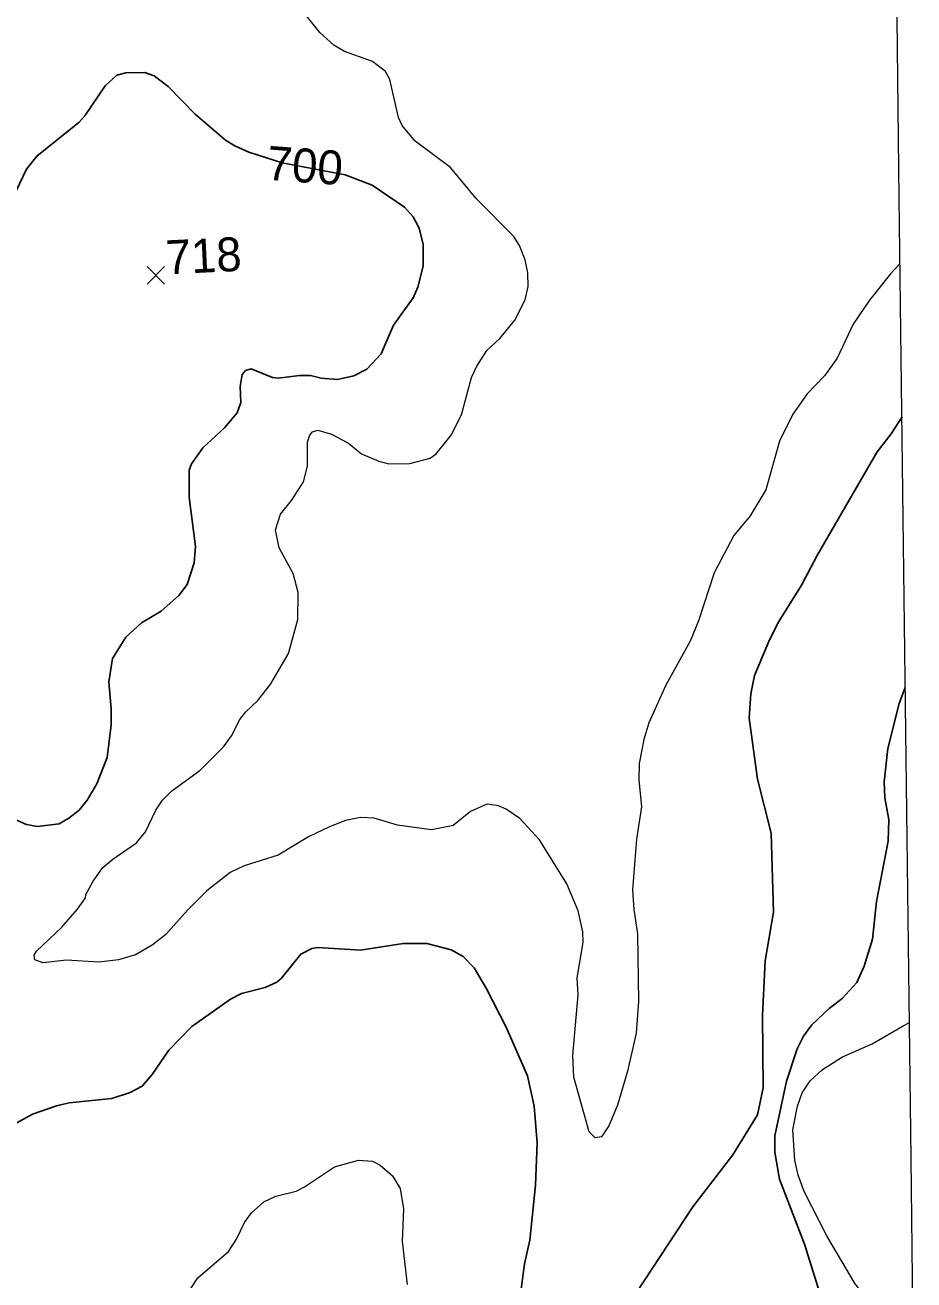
# Model space of a CAD drawing. Extents: x 265 to 291.4, y 7731.5 to 7759.6.
# Drawn here: x 289.153 to 291.245, y 7746.284 to 7749.237 of the extents above; entities that cross this region are included whole.
import ezdxf
from ezdxf.enums import TextEntityAlignment as Align

# ---------------------------------------------------------------- set-up
doc = ezdxf.new("R2010")
doc.units = 0
doc.header["$LTSCALE"] = 0.032
for name, color, linetype, lineweight in [('1', 7, 'Continuous', 25), ('2', 7, 'Continuous', 13), ('21', 7, 'Continuous', 25), ('61', 7, 'Continuous', 13), ('63', 7, 'Continuous', 25)]:
    doc.layers.add(name, color=color, linetype=linetype, lineweight=lineweight)

msp = doc.modelspace()

# ---------------------------------------------------------------- linework, layer by layer
at = {"layer": '1'}
for points in [[(289.1229, 7748.8292), (289.1563, 7748.8984), (289.1802, 7748.9286), (289.2797, 7749.0089), (289.2932, 7749.024), (289.3409, 7749.094), (289.3688, 7749.1195), (289.3902, 7749.1251), (289.4348, 7749.1259), (289.4563, 7749.1179), (289.4897, 7749.0924), (289.5533, 7749.0272), (289.6249, 7748.9667), (289.6464, 7748.9532), (289.6798, 7748.9381), (289.7577, 7748.9134), (289.9065, 7748.8848), (289.9694, 7748.8602), (290.0457, 7748.8084), (290.0664, 7748.7862), (290.0807, 7748.7592), (290.0902, 7748.721), (290.0895, 7748.6701), (290.0775, 7748.6207), (290.0664, 7748.5953), (290.0202, 7748.5308), (289.9908, 7748.4632), (289.9574, 7748.4274), (289.9264, 7748.4115), (289.8882, 7748.4028), (289.85, 7748.4059), (289.8246, 7748.4123), (289.7991, 7748.4123), (289.7482, 7748.4059), (289.7355, 7748.4075), (289.6846, 7748.4282), (289.6719, 7748.4242), (289.6639, 7748.4147), (289.6591, 7748.3869), (289.6607, 7748.3487), (289.6519, 7748.3248), (289.6225, 7748.289), (289.5708, 7748.2421), (289.5445, 7748.2047), (289.539, 7748.1896), (289.539, 7748.126), (289.5541, 7748.0098), (289.5509, 7747.9716), (289.5342, 7747.9207), (289.5143, 7747.8945), (289.473, 7747.8578), (289.4268, 7747.83), (289.3902, 7747.7966), (289.3584, 7747.7465), (289.3497, 7747.6916), (289.3552, 7747.628), (289.3552, 7747.5898), (289.3457, 7747.5134), (289.3218, 7747.4514), (289.2987, 7747.4132), (289.2797, 7747.3893), (289.2558, 7747.3702), (289.2327, 7747.3575), (289.1818, 7747.3511), (289.1564, 7747.3559), (289.0768, 7747.3901)], [(290.5906, 7746.2518), (290.725, 7746.4554), (290.8189, 7746.5779), (290.877, 7746.6718), (290.8905, 7746.7354), (290.8889, 7746.9057), (290.8945, 7747.0345), (290.9144, 7747.1491), (290.9088, 7747.3352), (290.877, 7747.4625), (290.8571, 7747.6057), (290.8611, 7747.663), (290.8698, 7747.7059), (290.9048, 7747.7903), (290.9271, 7747.8332), (290.9804, 7747.9191), (291.0178, 7747.9907), (291.1586, 7748.2325), (291.1912, 7748.2755), (291.217, 7748.3152)], [(291.2247, 7747.678), (291.2105, 7747.6407), (291.1833, 7747.5341), (291.1753, 7747.4562), (291.1769, 7747.418), (291.1856, 7747.3671), (291.1848, 7747.3161), (291.157, 7747.1746), (291.1475, 7747.0855), (291.1276, 7747.0218), (291.1109, 7746.9836), (291.0759, 7746.9462), (291.0456, 7746.9224), (291.0051, 7746.8842), (290.9852, 7746.8572), (290.9701, 7746.8277), (290.9454, 7746.7514), (290.9176, 7746.6225), (290.9176, 7746.5843), (290.9287, 7746.5207), (290.9876, 7746.3679), (291.0599, 7746.1372)], [(289.119, 7746.6455), (289.1699, 7746.6734), (289.2264, 7746.6933), (289.2566, 7746.7004), (289.3568, 7746.7108), (289.3998, 7746.7251), (289.4284, 7746.7394), (289.4523, 7746.7673), (289.4912, 7746.8245), (289.5453, 7746.8802), (289.636, 7746.9446), (289.6623, 7746.9574), (289.718, 7746.9717), (289.745, 7746.9844), (289.7562, 7746.994), (289.8015, 7747.0504), (289.8278, 7747.064), (289.8421, 7747.0663), (289.9423, 7747.06), (290.0425, 7747.0751), (290.0982, 7747.0751), (290.1555, 7747.0608), (290.1841, 7747.0449), (290.2096, 7747.0178), (290.2382, 7746.9701), (290.2851, 7746.8786), (290.3353, 7746.7641), (290.3512, 7746.6925), (290.3583, 7746.6066), (290.3543, 7746.5063), (290.3408, 7746.3775), (290.3281, 7746.3218)], [(290.3281, 7746.3218), (290.3146, 7746.2144), (290.2788, 7746.1213), (290.2462, 7746.0084), (290.243, 7745.9877), (290.2541, 7745.9773), (290.2756, 7745.9765)]]:
    msp.add_lwpolyline(points, dxfattribs=at)
at = {"layer": '2'}
for points in [[(289.823, 7748.2723), (289.8293, 7748.2795), (289.8421, 7748.2834), (289.8739, 7748.2747), (289.9137, 7748.2532), (289.9447, 7748.2278), (289.9853, 7748.2111), (290.0091, 7748.2047), (290.0585, 7748.2055), (290.1062, 7748.2182), (290.1205, 7748.2278), (290.1555, 7748.2723), (290.1802, 7748.3201), (290.204, 7748.4076), (290.2159, 7748.4346), (290.2398, 7748.4712), (290.27, 7748.4998), (290.3058, 7748.5428), (290.3297, 7748.5905), (290.3369, 7748.6223), (290.3361, 7748.6542), (290.3297, 7748.6844), (290.3168, 7748.7185), (290.3034, 7748.7393), (290.2144, 7748.8292), (290.1539, 7748.9023), (290.0712, 7748.9644), (290.0401, 7749.001), (290.0314, 7749.0201), (290.0115, 7749.1092), (290.0012, 7749.1283), (289.9702, 7749.1513), (289.9049, 7749.1752), (289.8795, 7749.1903), (289.8468, 7749.2197), (289.7991, 7749.2794)], [(291.2126, 7748.676), (291.19, 7748.6521), (291.1403, 7748.5897), (291.1021, 7748.5332), (291.0647, 7748.4529), (291.0345, 7748.4115), (290.9939, 7748.3694), (290.9597, 7748.3216), (290.9287, 7748.258), (290.8961, 7748.1435), (290.8595, 7748.0822), (290.8213, 7748.0361), (290.7752, 7747.9478), (290.7378, 7747.8348), (290.7187, 7747.7871), (290.6614, 7747.6837), (290.6209, 7747.5946), (290.6089, 7747.5556), (290.5986, 7747.4991), (290.5978, 7747.4609), (290.6041, 7747.3973), (290.5922, 7747.3209), (290.5827, 7747.2016), (290.5858, 7747.1555), (290.5946, 7747.0982), (290.597, 7746.9391), (290.5914, 7746.8643), (290.5707, 7746.7752), (290.5469, 7746.6949), (290.527, 7746.6464), (290.5095, 7746.6201), (290.4944, 7746.6177), (290.4808, 7746.632), (290.4443, 7746.7609), (290.4424, 7746.8117), (290.4546, 7746.955), (290.4522, 7746.9948), (290.4665, 7747.0775), (290.4657, 7747.103), (290.4546, 7747.1523), (290.4283, 7747.2159), (290.3639, 7747.3193), (290.317, 7747.3694), (290.2852, 7747.3917), (290.2669, 7747.3997), (290.2398, 7747.4036), (290.2016, 7747.3861), (290.1603, 7747.3535), (290.1094, 7747.3432), (290.0298, 7747.3543), (289.9741, 7747.3702), (289.9423, 7747.3718), (289.9073, 7747.3647), (289.8691, 7747.3503), (289.8198, 7747.3265), (289.7482, 7747.2835), (289.6687, 7747.2581), (289.6353, 7747.2422), (289.5804, 7747.1992), (289.535, 7747.1539), (289.4841, 7747.0966), (289.4523, 7747.0719), (289.4125, 7747.0489), (289.3727, 7747.0369), (289.3266, 7747.0314), (289.2502, 7747.0361), (289.1946, 7747.0298), (289.1755, 7747.0369), (289.1739, 7747.0481), (289.1794, 7747.0576), (289.2391, 7747.1141), (289.2765, 7747.1563), (289.2948, 7747.1833), (289.2956, 7747.1905), (289.3131, 7747.2223), (289.3361, 7747.2541), (289.3592, 7747.274), (289.4149, 7747.3122), (289.4364, 7747.3384), (289.4602, 7747.3893), (289.4761, 7747.4132), (289.4984, 7747.4347), (289.5645, 7747.4824), (289.6201, 7747.5381), (289.6384, 7747.5643), (289.6583, 7747.6025), (289.6726, 7747.6208), (289.7005, 7747.6471), (289.7315, 7747.6868), (289.7729, 7747.7584), (289.7951, 7747.838), (289.7959, 7747.9016), (289.784, 7747.9462), (289.7506, 7748.0066), (289.7426, 7748.0488)], [(289.7426, 7748.0488), (289.7538, 7748.0862), (289.78, 7748.118), (289.8079, 7748.1625), (289.8174, 7748.1991), (289.8174, 7748.2564), (289.823, 7748.2723)], [(291.2427, 7746.2019), (291.188, 7746.212), (291.1562, 7746.2255), (291.122, 7746.2558), (291.1069, 7746.2741), (291.0409, 7746.3854), (290.9868, 7746.492), (290.9725, 7746.5302), (290.9645, 7746.5652), (290.9597, 7746.6368), (290.9709, 7746.6925), (290.982, 7746.7243), (291.0011, 7746.7521), (291.0297, 7746.7792), (291.0767, 7746.8086), (291.1467, 7746.8396), (291.2199, 7746.8818), (291.2343, 7746.8892)], [(289.5279, 7746.2407), (289.5597, 7746.2884), (289.6313, 7746.3504), (289.6504, 7746.3791), (289.6695, 7746.4188), (289.6854, 7746.4411), (289.7148, 7746.4674), (289.7434, 7746.4809), (289.7912, 7746.4928), (289.8103, 7746.5024), (289.8811, 7746.5501), (289.9375, 7746.5652), (289.9709, 7746.5628), (289.9885, 7746.5533), (290.0179, 7746.5286), (290.0354, 7746.4984), (290.0433, 7746.4507), (290.0401, 7746.3743), (290.0521, 7746.2725)]]:
    msp.add_lwpolyline(points, dxfattribs=at)
at = {"layer": '21'}
for p, q in [((289.4399, 7748.6687), (289.4811, 7748.6275)), ((289.4811, 7748.6687), (289.4399, 7748.6275))]:
    msp.add_line(p, q, dxfattribs=at)
at = {"layer": '63', "lineweight": 13}
msp.add_lwpolyline([(291.245, 7746.0054), (291.2382, 7746.5703), (291.2313, 7747.1352), (291.2244, 7747.7001), (291.2176, 7748.265), (291.2107, 7748.8299), (291.2039, 7749.3947), (291.197, 7749.9596), (291.1902, 7750.5245), (291.1833, 7751.0894), (291.1765, 7751.6543), (291.1696, 7752.2192), (291.1628, 7752.784), (291.1559, 7753.3489)], dxfattribs=at)

# ---------------------------------------------------------------- texts
at = {"layer": '61'}
for s, rotation, p in [('700', 355.81, (289.8085, 7748.8669)), ('718', 2.757, (289.5749, 7748.6547))]:
    msp.add_text(s, height=0.08, rotation=rotation, dxfattribs=at).set_placement(p, align=Align.CENTER)

doc.saveas('drawing.dxf')
